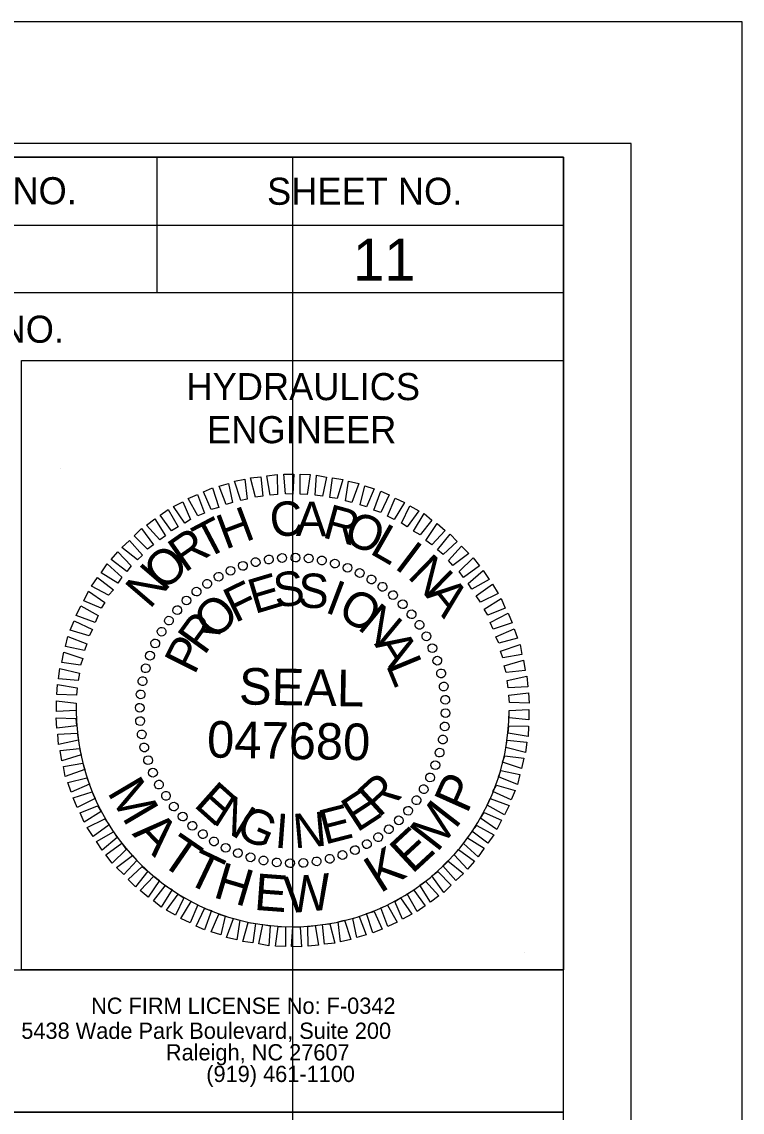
# Model space of a CAD drawing. Extents: x 270 to 1290, y -4845 to -4185.
# Drawn here: x 1210 to 1289.8, y -4305.5 to -4184.8 of the extents above; entities that cross this region are included whole.
import ezdxf

# ---------------------------------------------------------------- set-up
doc = ezdxf.new("R2010")
doc.units = 0
for name, color, linetype in [('Old_Level_2', 7, 'Continuous'), ('Prop DSN Text', 7, 'Continuous'), ('Scratch_Level_0', 7, 'Continuous'), ('Scratch_Level_1', 7, 'Continuous'), ('Sheet Block Title CELL', 7, 'Continuous'), ('Sheet Border Standard 30in CELL', 7, 'Continuous'), ('Sheet Cutting Line CELL', 7, 'Continuous'), ('Sheet Data Field CELL', 7, 'Continuous'), ('Sheet Plot Border Inside CELL', 7, 'Continuous'), ('Sheet Plot Border Outside CELL', 7, 'Continuous'), ('Sheet Profile CELL', 7, 'Continuous'), ('Sheet Sticker Exception Certification CELL', 7, 'Continuous')]:
    doc.layers.add(name, color=color, linetype=linetype)

msp = doc.modelspace()

# ---------------------------------------------------------------- linework, layer by layer
at = {"layer": 'Old_Level_2'}
for p, q in [((1214.31, -4234.23), (1214.31, -4234.23)), ((1238.85, -4244.12), (1238.85, -4244.12)), ((1240.33, -4244.09), (1240.33, -4244.09)), ((1241.82, -4244.19), (1241.82, -4244.19)), ((1234.5, -4245), (1234.5, -4245)), ((1235.91, -4244.59), (1235.91, -4244.59)), ((1237.4, -4244.32), (1237.4, -4244.32)), ((1243.27, -4244.43), (1243.27, -4244.43)), ((1244.69, -4244.73), (1244.69, -4244.73)), ((1246.11, -4245.2), (1246.11, -4245.2)), ((1231.83, -4246.21), (1231.83, -4246.21)), ((1233.15, -4245.54), (1233.15, -4245.54)), ((1247.46, -4245.81), (1247.46, -4245.81)), ((1248.77, -4246.48), (1248.77, -4246.48)), ((1229.37, -4247.83), (1229.37, -4247.83)), ((1230.55, -4246.99), (1230.55, -4246.99)), ((1249.99, -4247.33), (1249.99, -4247.33)), ((1228.25, -4248.85), (1228.25, -4248.85)), ((1251.17, -4248.24), (1251.17, -4248.24)), ((1227.24, -4249.89), (1227.24, -4249.89)), ((1252.21, -4249.25), (1252.21, -4249.25)), ((1226.33, -4251.07), (1226.33, -4251.07)), ((1253.23, -4250.37), (1253.23, -4250.37)), ((1254.07, -4251.55), (1254.07, -4251.55)), ((1225.48, -4252.29), (1225.48, -4252.29)), ((1224.81, -4253.61), (1224.81, -4253.61)), ((1254.85, -4252.83), (1254.85, -4252.83)), ((1224.2, -4254.96), (1224.2, -4254.96)), ((1255.52, -4254.15), (1255.52, -4254.15)), ((1223.73, -4256.37), (1223.73, -4256.37)), ((1256.06, -4255.5), (1256.06, -4255.5)), ((1256.47, -4256.91), (1256.47, -4256.91)), ((1223.43, -4257.79), (1223.43, -4257.79)), ((1256.74, -4258.4), (1256.74, -4258.4)), ((1223.19, -4259.24), (1223.19, -4259.24)), ((1256.94, -4259.85), (1256.94, -4259.85)), ((1223.09, -4260.73), (1223.09, -4260.73)), ((1240.03, -4261.03), (1240.03, -4261.03)), ((1223.12, -4262.21), (1223.12, -4262.21)), ((1256.97, -4261.33), (1256.97, -4261.33)), ((1256.87, -4262.82), (1256.87, -4262.82)), ((1223.32, -4263.66), (1223.32, -4263.66)), ((1256.64, -4264.27), (1256.64, -4264.27)), ((1223.59, -4265.15), (1223.59, -4265.15)), ((1256.33, -4265.69), (1256.33, -4265.69)), ((1224, -4266.57), (1224, -4266.57)), ((1255.86, -4267.11), (1255.86, -4267.11)), ((1224.54, -4267.92), (1224.54, -4267.92)), ((1255.25, -4268.46), (1255.25, -4268.46)), ((1225.21, -4269.23), (1225.21, -4269.23)), ((1225.99, -4270.51), (1225.99, -4270.51)), ((1254.58, -4269.77), (1254.58, -4269.77)), ((1226.83, -4271.7), (1226.83, -4271.7)), ((1253.73, -4270.99), (1253.73, -4270.99)), ((1227.85, -4272.81), (1227.85, -4272.81)), ((1251.81, -4273.21), (1251.81, -4273.21)), ((1252.82, -4272.17), (1252.82, -4272.17)), ((1228.89, -4273.82), (1228.89, -4273.82)), ((1250.7, -4274.23), (1250.7, -4274.23)), ((1230.07, -4274.73), (1230.07, -4274.73)), ((1231.29, -4275.58), (1231.29, -4275.58)), ((1249.51, -4275.07), (1249.51, -4275.07)), ((1232.61, -4276.25), (1232.61, -4276.25)), ((1233.96, -4276.86), (1233.96, -4276.86)), ((1246.92, -4276.52), (1246.92, -4276.52)), ((1248.23, -4275.85), (1248.23, -4275.85)), ((1235.37, -4277.33), (1235.37, -4277.33)), ((1236.79, -4277.64), (1236.79, -4277.64)), ((1238.24, -4277.87), (1238.24, -4277.87)), ((1239.73, -4277.97), (1239.73, -4277.97)), ((1241.21, -4277.94), (1241.21, -4277.94)), ((1242.66, -4277.74), (1242.66, -4277.74)), ((1244.15, -4277.47), (1244.15, -4277.47)), ((1245.57, -4277.06), (1245.57, -4277.06)), ((1265.75, -4287.83), (1265.75, -4287.83))]:
    msp.add_line(p, q, dxfattribs=at)
for points in [[(1234.29, -4237.78), (1233.58, -4235.65), (1234.73, -4235.41), (1235, -4237.61)], [(1235.91, -4237.41), (1235.37, -4235.25), (1236.49, -4235.14), (1236.72, -4237.3)], [(1237.53, -4237.2), (1237.16, -4235.04), (1238.31, -4234.91), (1238.34, -4237.1)], [(1239.22, -4237.03), (1239.05, -4234.84), (1240.17, -4234.87), (1240.03, -4237.07)], [(1240.84, -4237.07), (1240.84, -4234.87), (1241.95, -4234.91), (1241.65, -4237.1)], [(1242.53, -4237.17), (1242.66, -4234.98), (1243.78, -4235.18), (1243.34, -4237.3)], [(1244.15, -4237.44), (1244.45, -4235.28), (1245.57, -4235.45), (1244.96, -4237.54)], [(1245.87, -4237.81), (1246.21, -4235.62), (1247.35, -4235.89), (1246.58, -4237.98)], [(1231.02, -4238.76), (1230.14, -4236.8), (1231.15, -4236.39), (1231.86, -4238.55)], [(1232.67, -4238.22), (1231.9, -4236.19), (1232.94, -4235.89), (1233.38, -4237.98)], [(1247.49, -4238.25), (1248, -4236.16), (1249.04, -4236.49), (1248.2, -4238.49)], [(1249.01, -4238.86), (1249.78, -4236.73), (1250.73, -4237.14), (1249.78, -4239.09)], [(1228.08, -4240.27), (1226.83, -4238.45), (1227.88, -4237.91), (1228.72, -4239.87)], [(1229.53, -4239.46), (1228.45, -4237.57), (1229.5, -4237.1), (1230.28, -4239.16)], [(1250.53, -4239.5), (1251.37, -4237.51), (1252.42, -4237.98), (1251.27, -4239.87)], [(1226.6, -4241.12), (1225.35, -4239.4), (1226.23, -4238.76), (1227.34, -4240.71)], [(1252.08, -4240.27), (1252.99, -4238.35), (1254, -4238.92), (1252.72, -4240.68)], [(1253.4, -4241.19), (1254.58, -4239.23), (1255.45, -4239.94), (1254.14, -4241.59)], [(1225.32, -4242.13), (1223.86, -4240.51), (1224.78, -4239.8), (1225.96, -4241.69)], [(1254.78, -4242.2), (1256.03, -4240.34), (1256.91, -4241.08), (1255.42, -4242.67)], [(1223.97, -4243.18), (1222.48, -4241.69), (1223.29, -4240.88), (1224.61, -4242.7)], [(1256.06, -4243.24), (1257.45, -4241.49), (1258.26, -4242.3), (1256.7, -4243.75)], [(1222.85, -4244.36), (1221.13, -4242.97), (1221.97, -4242.2), (1223.39, -4243.82)], [(1257.28, -4244.43), (1258.73, -4242.84), (1259.54, -4243.65), (1257.78, -4244.97)], [(1221.67, -4245.64), (1219.92, -4244.32), (1220.66, -4243.45), (1222.14, -4245.03)], [(1258.46, -4245.64), (1260.01, -4244.12), (1260.72, -4245.03), (1258.93, -4246.32)], [(1220.66, -4246.92), (1218.84, -4245.78), (1219.48, -4244.8), (1221.1, -4246.28)], [(1219.65, -4248.27), (1217.76, -4247.26), (1218.43, -4246.32), (1220.19, -4247.67)], [(1259.47, -4246.96), (1261.12, -4245.54), (1261.77, -4246.52), (1259.88, -4247.6)], [(1218.84, -4249.72), (1216.91, -4248.88), (1217.42, -4247.83), (1219.24, -4249.08)], [(1260.35, -4248.34), (1262.14, -4247.06), (1262.78, -4248.07), (1260.82, -4249.02)], [(1261.23, -4249.83), (1263.12, -4248.64), (1263.55, -4249.69), (1261.63, -4250.47)], [(1218.16, -4251.28), (1216.07, -4250.5), (1216.57, -4249.45), (1218.5, -4250.53)], [(1261.9, -4251.28), (1263.89, -4250.26), (1264.33, -4251.34), (1262.24, -4252.02)], [(1217.49, -4252.76), (1215.39, -4252.15), (1215.83, -4251.11), (1217.86, -4252.05)], [(1262.51, -4252.86), (1264.57, -4251.99), (1264.94, -4253.03), (1262.85, -4253.57)], [(1216.98, -4254.38), (1214.89, -4253.94), (1215.12, -4252.83), (1217.25, -4253.67)], [(1263.05, -4254.48), (1265.21, -4253.71), (1265.41, -4254.82), (1263.28, -4255.19)], [(1216.54, -4256), (1214.45, -4255.73), (1214.68, -4254.58), (1216.81, -4255.29)], [(1216.27, -4257.72), (1214.11, -4257.52), (1214.25, -4256.37), (1216.44, -4256.91)], [(1263.45, -4256.1), (1265.58, -4255.46), (1265.78, -4256.61), (1263.66, -4256.81)], [(1263.76, -4257.72), (1265.95, -4257.25), (1266.05, -4258.4), (1263.89, -4258.53)], [(1216.1, -4259.34), (1213.91, -4259.28), (1213.98, -4258.16), (1216.17, -4258.53)], [(1216.07, -4261.03), (1213.87, -4261.13), (1213.87, -4259.98), (1216.07, -4260.22)], [(1263.96, -4259.34), (1266.15, -4259.07), (1266.22, -4260.22), (1264.03, -4260.15)], [(1263.99, -4261.03), (1266.19, -4260.93), (1266.19, -4262.08), (1263.99, -4261.84)], [(1216.1, -4262.72), (1213.91, -4262.99), (1213.84, -4261.84), (1216.03, -4261.91)], [(1216.3, -4264.34), (1214.11, -4264.81), (1214.01, -4263.66), (1216.17, -4263.53)], [(1263.96, -4262.72), (1266.15, -4262.79), (1266.09, -4263.9), (1263.89, -4263.53)], [(1263.79, -4264.34), (1265.95, -4264.54), (1265.82, -4265.69), (1263.62, -4265.15)], [(1216.61, -4265.96), (1214.48, -4266.6), (1214.28, -4265.45), (1216.41, -4265.25)], [(1263.52, -4266.06), (1265.61, -4266.33), (1265.38, -4267.48), (1263.25, -4266.77)], [(1217.01, -4267.58), (1214.85, -4268.35), (1214.65, -4267.24), (1216.78, -4266.87)], [(1263.08, -4267.68), (1265.17, -4268.12), (1264.94, -4269.23), (1262.81, -4268.39)], [(1217.55, -4269.2), (1215.49, -4270.08), (1215.12, -4269.03), (1217.22, -4268.49)], [(1262.58, -4269.3), (1264.67, -4269.91), (1264.23, -4270.95), (1262.2, -4270.01)], [(1218.16, -4270.78), (1216.17, -4271.8), (1215.73, -4270.72), (1217.82, -4270.04)], [(1261.9, -4270.78), (1263.99, -4271.56), (1263.49, -4272.61), (1261.56, -4271.53)], [(1218.84, -4272.24), (1216.95, -4273.42), (1216.51, -4272.37), (1218.43, -4271.59)], [(1219.71, -4273.72), (1217.92, -4275), (1217.28, -4273.99), (1219.24, -4273.05)], [(1261.23, -4272.34), (1263.15, -4273.18), (1262.64, -4274.23), (1260.82, -4272.98)], [(1220.59, -4275.1), (1218.94, -4276.52), (1218.3, -4275.54), (1220.19, -4274.46)], [(1260.42, -4273.79), (1262.31, -4274.8), (1261.63, -4275.75), (1259.88, -4274.4)], [(1259.4, -4275.14), (1261.23, -4276.29), (1260.58, -4277.26), (1258.96, -4275.78)], [(1221.6, -4276.42), (1220.05, -4277.94), (1219.34, -4277.03), (1221.13, -4275.75)], [(1258.39, -4276.42), (1260.15, -4277.74), (1259.4, -4278.61), (1257.92, -4277.03)], [(1222.78, -4277.64), (1221.33, -4279.22), (1220.52, -4278.41), (1222.28, -4277.1)], [(1257.21, -4277.7), (1258.93, -4279.09), (1258.09, -4279.86), (1256.67, -4278.24)], [(1224, -4278.82), (1222.62, -4280.57), (1221.81, -4279.76), (1223.36, -4278.31)], [(1256.1, -4278.88), (1257.58, -4280.37), (1256.77, -4281.18), (1255.45, -4279.36)], [(1225.28, -4279.86), (1224.03, -4281.72), (1223.16, -4280.98), (1224.64, -4279.39)], [(1226.67, -4280.88), (1225.48, -4282.83), (1224.61, -4282.12), (1225.92, -4280.47)], [(1254.75, -4279.93), (1256.2, -4281.55), (1255.29, -4282.26), (1254.1, -4280.37)], [(1227.98, -4281.79), (1227.07, -4283.71), (1226.06, -4283.14), (1227.34, -4281.38)], [(1253.46, -4280.94), (1254.71, -4282.66), (1253.83, -4283.31), (1252.72, -4281.35)], [(1229.53, -4282.56), (1228.69, -4284.55), (1227.64, -4284.08), (1228.79, -4282.19)], [(1231.05, -4283.2), (1230.28, -4285.33), (1229.33, -4284.93), (1230.28, -4282.97)], [(1250.53, -4282.6), (1251.61, -4284.49), (1250.56, -4284.96), (1249.78, -4282.9)], [(1251.98, -4281.79), (1253.23, -4283.61), (1252.18, -4284.15), (1251.34, -4282.19)], [(1232.57, -4283.81), (1232.07, -4285.9), (1231.02, -4285.57), (1231.86, -4283.58)], [(1234.19, -4284.25), (1233.85, -4286.44), (1232.71, -4286.17), (1233.48, -4284.08)], [(1247.39, -4283.85), (1248.16, -4285.87), (1247.12, -4286.17), (1246.68, -4284.08)], [(1249.04, -4283.31), (1249.92, -4285.26), (1248.91, -4285.67), (1248.2, -4283.51)], [(1235.91, -4284.62), (1235.61, -4286.78), (1234.5, -4286.61), (1235.1, -4284.52)], [(1237.53, -4284.89), (1237.4, -4287.09), (1236.28, -4286.88), (1236.72, -4284.76)], [(1239.22, -4284.99), (1239.22, -4287.19), (1238.11, -4287.15), (1238.41, -4284.96)], [(1240.84, -4285.03), (1241.01, -4287.22), (1239.9, -4287.19), (1240.03, -4284.99)], [(1242.53, -4284.86), (1242.9, -4287.02), (1241.75, -4287.15), (1241.72, -4284.96)], [(1244.15, -4284.66), (1244.69, -4286.82), (1243.57, -4286.92), (1243.34, -4284.76)], [(1245.77, -4284.28), (1246.48, -4286.41), (1245.33, -4286.65), (1245.06, -4284.45)]]:
    msp.add_lwpolyline(points, close=True, dxfattribs=at)
for centre, major_axis in [((1235.93, -4244.6), (-0.118, 0.472)), ((1237.38, -4244.31), (-0.076, 0.48)), ((1238.85, -4244.14), (-0.034, 0.485)), ((1240.33, -4244.1), (0.008, 0.486)), ((1241.8, -4244.19), (0.051, 0.483)), ((1243.26, -4244.41), (0.093, 0.477)), ((1244.7, -4244.76), (0.134, 0.467)), ((1233.14, -4245.56), (-0.198, 0.444)), ((1234.52, -4245.02), (-0.158, 0.46)), ((1246.1, -4245.23), (0.174, 0.454)), ((1247.45, -4245.81), (0.213, 0.437)), ((1230.56, -4247), (-0.272, 0.403)), ((1231.82, -4246.22), (-0.236, 0.425)), ((1248.75, -4246.52), (0.25, 0.417)), ((1229.38, -4247.87), (-0.306, 0.378)), ((1249.98, -4247.33), (0.286, 0.393)), ((1251.14, -4248.25), (0.319, 0.367)), ((1228.27, -4248.85), (-0.338, 0.35)), ((1252.21, -4249.27), (0.35, 0.338)), ((1227.25, -4249.92), (-0.367, 0.319)), ((1253.19, -4250.38), (0.378, 0.306)), ((1226.33, -4251.08), (-0.393, 0.286)), ((1254.07, -4251.56), (0.403, 0.272)), ((1225.52, -4252.31), (-0.417, 0.25)), ((1254.84, -4252.82), (0.425, 0.236)), ((1224.81, -4253.61), (-0.437, 0.213)), ((1255.5, -4254.14), (0.444, 0.198)), ((1224.23, -4254.96), (-0.454, 0.174)), ((1256.04, -4255.52), (0.46, 0.158)), ((1223.76, -4256.36), (-0.467, 0.134)), ((1256.46, -4256.93), (0.472, 0.118)), ((1223.41, -4257.8), (-0.477, 0.093)), ((1223.19, -4259.26), (-0.483, 0.051)), ((1256.75, -4258.38), (0.48, 0.076)), ((1256.92, -4259.85), (0.485, 0.034)), ((1223.1, -4260.73), (-0.486, 0.008)), ((1256.96, -4261.33), (0.486, -0.008)), ((1223.14, -4262.21), (-0.485, -0.034)), ((1256.87, -4262.8), (0.483, -0.051)), ((1223.31, -4263.68), (-0.48, -0.076)), ((1223.6, -4265.13), (-0.472, -0.118)), ((1256.65, -4264.26), (0.477, -0.093)), ((1224.02, -4266.54), (-0.46, -0.158)), ((1256.3, -4265.7), (0.467, -0.134)), ((1255.83, -4267.1), (0.454, -0.174)), ((1224.56, -4267.92), (-0.444, -0.198)), ((1255.25, -4268.45), (0.437, -0.213)), ((1225.22, -4269.24), (-0.425, -0.236)), ((1254.54, -4269.75), (0.417, -0.25)), ((1226, -4270.5), (-0.403, -0.272)), ((1253.73, -4270.98), (0.393, -0.286)), ((1226.87, -4271.68), (-0.378, -0.306)), ((1252.81, -4272.14), (0.367, -0.319)), ((1227.85, -4272.79), (-0.35, -0.338)), ((1228.92, -4273.81), (-0.319, -0.367)), ((1251.79, -4273.21), (0.338, -0.35)), ((1230.08, -4274.73), (-0.286, -0.393)), ((1249.5, -4275.06), (0.272, -0.403)), ((1250.68, -4274.19), (0.306, -0.378)), ((1231.31, -4275.54), (-0.25, -0.417)), ((1232.61, -4276.25), (-0.213, -0.437)), ((1248.24, -4275.84), (0.236, -0.425)), ((1233.96, -4276.83), (-0.174, -0.454)), ((1235.36, -4277.3), (-0.134, -0.467)), ((1244.13, -4277.46), (0.118, -0.472)), ((1245.54, -4277.04), (0.158, -0.46)), ((1246.92, -4276.5), (0.198, -0.444)), ((1236.8, -4277.65), (-0.093, -0.477)), ((1238.26, -4277.87), (-0.051, -0.483)), ((1239.73, -4277.96), (-0.008, -0.486)), ((1241.21, -4277.92), (0.034, -0.485)), ((1242.68, -4277.75), (0.076, -0.48))]:
    msp.add_ellipse(centre, major_axis=major_axis, ratio=0.999708, dxfattribs=at)
at = {"layer": 'Scratch_Level_0'}
msp.add_arc((1240.03, -4261.03), 23.96, 180, 360, dxfattribs=at)
at = {"layer": 'Scratch_Level_1'}
msp.add_lwpolyline([(850, -4199.75), (1240, -4199.75), (1240, -4499.75), (850, -4499.75)], close=True, dxfattribs=at)
at = {"layer": 'Sheet Block Title CELL'}
msp.add_lwpolyline([(1149.97, -4289.78), (1269.97, -4289.78), (1269.97, -4305.53), (1149.97, -4305.53)], close=True, dxfattribs=at)
at = {"layer": 'Sheet Border Standard 30in CELL'}
msp.add_line((1270, -4214.78), (1270, -4222.28), dxfattribs=at)
msp.add_lwpolyline([(1210, -4222.28), (1270, -4222.28), (1270, -4289.78), (1210, -4289.78)], close=True, dxfattribs=at)
at = {"layer": 'Sheet Cutting Line CELL'}
for p, q in [((1289.8, -4184.75), (269.8, -4184.75)), ((1289.8, -4844.75), (1289.8, -4184.75))]:
    msp.add_line(p, q, dxfattribs=at)
at = {"layer": 'Sheet Plot Border Inside CELL'}
msp.add_lwpolyline([(277.6, -4831.28), (1277.5, -4831.28), (1277.5, -4198.22), (277.6, -4198.22)], close=True, dxfattribs=at)
at = {"layer": 'Sheet Plot Border Outside CELL'}
msp.add_lwpolyline([(269.8, -4844.75), (1289.8, -4844.75), (1289.8, -4184.75), (269.8, -4184.75)], close=True, dxfattribs=at)
at = {"layer": 'Sheet Profile CELL'}
for p, q in [((1225, -4199.78), (1225, -4214.78)), ((1149.97, -4207.28), (1270, -4207.28))]:
    msp.add_line(p, q, dxfattribs=at)
for points in [[(1270, -4199.75), (370, -4199.75), (370, -4829.75), (1270, -4829.75)], [(1149.97, -4199.75), (1270, -4199.75), (1270, -4214.78), (1149.97, -4214.78)]]:
    msp.add_lwpolyline(points, close=True, dxfattribs=at)
at = {"layer": 'Sheet Sticker Exception Certification CELL'}
msp.add_line((1149.97, -4305.53), (1269.99, -4305.53), dxfattribs=at)

# ---------------------------------------------------------------- texts
at = {"layer": 'Old_Level_2'}
for s, height, rotation, p in [('C', 3.81, 6.2199, (1237.7, -4241.89)), ('A', 3.81, 359.0203, (1240.37, -4241.69)), ('R', 3.83, 344.6211, (1243.2, -4241.83)), ('H', 3.85, 20.6195, (1232.57, -4243.24)), ('O', 3.86, 337.4212, (1245.46, -4242.33)), ('T', 3.88, 27.8198, (1230.38, -4244.36)), ('L', 3.89, 330.2209, (1248.43, -4243.58)), ('R', 3.91, 35.0205, (1228.08, -4245.84)), ('O', 3.93, 42.2217, (1225.75, -4247.94)), ('I', 3.92, 323.0201, (1251.17, -4245.2)), ('N', 3.93, 315.8189, (1252.62, -4246.25)), ('N', 3.93, 49.4235, (1224.2, -4249.89)), ('S', 3.81, 7.2556, (1238.14, -4249.66)), ('F', 3.88, 25.967, (1233.65, -4251.38)), ('E', 3.84, 16.6111, (1235.81, -4250.37)), ('S', 3.81, 357.9004, (1240.57, -4249.62)), ('I', 3.86, 339.1896, (1243.47, -4250.1)), ('O', 3.89, 329.8335, (1244.82, -4250.57)), ('A', 3.93, 308.6172, (1254.61, -4248.24)), ('O', 3.93, 44.6812, (1231.42, -4253.37)), ('R', 3.93, 54.0397, (1230.24, -4255.02)), ('N', 3.92, 320.4766, (1247.08, -4251.92)), ('P', 3.9, 63.3989, (1229.16, -4257.18)), ('A', 3.92, 301.7603, (1249.01, -4253.67)), ('L', 3.88, 292.4009, (1250.32, -4256)), ('SEAL', 4.049, 359, (1234.06, -4260.36)), ('047680', 4.05, 359, (1230.52, -4266.24)), ('M', 4.16, 300.5946, (1219.43, -4270.08)), ('R', 3.93, 42.4814, (1249.55, -4273.01)), ('P', 4.13, 65.9822, (1259.34, -4272.58)), ('E', 3.93, 318.2769, (1228.96, -4271.59)), ('E', 3.9, 33.1241, (1247.15, -4274.6)), ('N', 3.9, 327.634, (1230.99, -4273.42)), ('G', 3.86, 336.9902, (1233.55, -4274.94)), ('E', 3.83, 14.4118, (1243.57, -4275.91)), ('M', 4.18, 52.1673, (1256.02, -4276.86)), ('A', 4.18, 314.4095, (1222.18, -4274.74)), ('I', 3.81, 355.7012, (1237.97, -4276.22)), ('N', 3.81, 5.0564, (1240.23, -4276.32)), ('E', 4.18, 42.8526, (1253.25, -4279.24)), ('T', 4.16, 325.4865, (1225.15, -4277.91)), ('T', 4.12, 334.4865, (1227.98, -4280.03)), ('K', 4.15, 32.342, (1249.71, -4281.35)), ('H', 4.08, 343.4865, (1231.1, -4281.69)), ('E', 4.05, 355.7279, (1235.68, -4283.11)), ('W', 4.05, 5.0426, (1239.31, -4283.52))]:
    msp.add_text(s, height=height, rotation=rotation, dxfattribs=at).set_placement(p)
at = {"layer": 'Prop DSN Text'}
for s, p in [('NC FIRM LICENSE No: F-0342', (1217.71, -4294.64)), ('5438 Wade Park Boulevard, Suite 200', (1209.98, -4297.41)), ('Raleigh, NC 27607', (1225.99, -4299.8)), ('(919) 461-1100', (1230.46, -4302.19))]:
    msp.add_text(s, height=1.8, rotation=0, dxfattribs=at).set_placement(p)
at = {"layer": 'Sheet Border Standard 30in CELL'}
for s, height, p in [('R/W SHEET NO.', 3.0001, (1184.17, -4220.3)), ('HYDRAULICS', 3, (1228.27, -4226.66)), ('ENGINEER', 3, (1230.55, -4231.43))]:
    msp.add_text(s, height=height, rotation=0, dxfattribs=at).set_placement(p)
at = {"layer": 'Sheet Data Field CELL'}
msp.add_text('11', height=4.65, dxfattribs=at).set_placement((1246.71, -4213.42))
at = {"layer": 'Sheet Profile CELL'}
for s, height, p in [('PROJECT REFERENCE NO.', 3.0001, (1163.3, -4204.96)), ('SHEET NO.', 3, (1237.19, -4205.02))]:
    msp.add_text(s, height=height, dxfattribs=at).set_placement(p)

doc.saveas('drawing.dxf')
